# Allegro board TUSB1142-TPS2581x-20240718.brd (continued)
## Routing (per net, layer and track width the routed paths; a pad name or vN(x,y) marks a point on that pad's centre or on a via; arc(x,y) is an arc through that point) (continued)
A_UDN_SW: length 33.1
  TOP w0.127: v1(31.88,2.04) 32.13,2.3 32.13,3 32.04,3.09 F_TYPEC2.B7 ; v1(32.41,7.51) 33.24,7.51 33.66,7.09 33.66,6.43 32.79,5.55 F_TYPEC2.A7
  BOTTOM w0.127: v1(31.88,2.04) 32.13,2.29 32.13,2.91 30.45,4.59 30.45,6.7 31.27,7.51 v1(32.41,7.51) 32.82,7.1 33.14,7.1 33.62,7.58 33.62,8.94 33.44,9.12 33.44,9.5 33.62,9.68 33.62,10.06 33.44,10.24 33.44,10.62 33.62,10.8 33.62,11.18 33.44,11.36 33.44,11.74 33.62,11.91 33.62,13.76 34.6,14.73 34.6,14.98 34.87,15.25 35.12,15.25 35.39,15.52 35.39,15.77 35.66,16.04 35.91,16.04 36.19,16.32 36.84,16.32 37.01,16.5 37.4,16.5 37.57,16.32 38.6,16.32 40,14.93 U0905.1 41.37,14.93 42.16,14.14 42.41,14.14 L0901.4 42.76,14.48 R0905.2
A_UDP_SW: length 33.1
  TOP w0.127: F_TYPEC2.A6 32.29,5.66 32.6,5.97 32.77,5.97 33.36,6.56 33.36,6.96 33.11,7.21 32.74,7.21 32.41,6.88 v1(32.41,6.7) ; F_TYPEC2.B6 32.54,3.09 32.44,2.99 32.44,2.3 v1(32.69,2.04)
  BOTTOM w0.127: v1(32.69,2.04) 32.43,2.3 32.43,3.04 32.09,3.38 32.09,3.63 31.82,3.9 31.57,3.9 30.75,4.72 30.75,5.07 30.93,5.25 30.93,5.63 30.75,5.8 30.75,6.57 31.39,7.21 31.9,7.21 v1(32.41,6.7) 32.51,6.8 33.27,6.8 33.93,7.46 33.93,13.63 36.32,16.02 38.48,16.02 39.92,14.57 39.92,13.94 U0905.3 41.37,13.05 42.16,13.83 42.41,13.83 L0901.3 42.76,13.49 R0906.2
A_URXN_SW1_R: length 12.7
  TOP w0.127: F_TYPEC2.B10 30.54,3.09 30.45,3.01 30.45,2.29 v1(30.7,2.04) ; C0904.2 29.5,11.69 29.5,11.41 R0901.1 29.5,10.98 29.5,10.24 29.59,10.14 U0902.9 U0902.2 29.59,8.66 29.51,8.57 29.51,7.87 v1(29.75,7.63)
  BOTTOM w0.127: v1(30.7,2.04) 30.45,2.29 30.45,3.67 29.46,4.67 29.46,7.34 v1(29.75,7.63)
A_URXN_SW2_R: length 10.3
  TOP w0.127: F_TYPEC2.A10 34.29,5.52 34.38,5.62 34.38,7.07 35.41,8.1 35.41,8.54 35.32,8.64 U0901.1 U0901.10 35.32,10.14 35.41,10.24 35.41,13.52 R0903.1 35.41,13.95 35.41,14.36 C0911.2
A_URXP_SW1_R: length 12.8
  TOP w0.127: F_TYPEC2.B11 30.04,3.09 30.14,2.98 30.14,2.3 v1(29.88,2.04) ; C0912.2 29.19,11.69 29.19,11.41 R0902.1 29.19,10.98 29.19,10.24 29.09,10.14 U0902.10 U0902.1 29.09,8.69 29.2,8.58 29.2,7.89 v1(28.94,7.63)
  BOTTOM w0.127: v1(29.88,2.04) 30.14,2.3 30.14,3.55 29.15,4.54 29.15,7.41 v1(28.94,7.63)
A_URXP_SW2_R: length 10.3
  TOP w0.127: F_TYPEC2.A11 34.79,5.52 34.69,5.62 34.69,6.95 35.72,7.98 35.72,8.56 35.82,8.66 U0901.2 U0901.9 35.82,10.09 35.72,10.19 35.72,13.52 R0904.1 35.72,13.95 35.72,14.36 C0919.2
A_UTXN_SW1_R: length 8.9
  TOP w0.127: C0914.2 33.36,11.31 33.36,10.94 33.03,10.61 31.15,10.61 31,10.46 31,10.24 31.09,10.14 U0902.6 U0902.5 31.09,8.69 31.01,8.61 31.01,6.42 30.69,6.1 30.69,5.64 30.79,5.55 F_TYPEC2.A3
A_UTXN_SW2_R: length 12.4
  TOP w0.127: v1(33.88,2.04) 34.13,2.29 34.13,3 34.04,3.09 F_TYPEC2.B3 ; C0910.2 36.91,10.8 36.91,10.27 36.82,10.17 U0901.7 U0901.4 36.82,8.66 36.93,8.55 36.93,7.87 v1(36.66,7.6)
  BOTTOM w0.127: v1(33.88,2.04) 34.13,2.29 34.13,3.95 35.86,5.68 35.86,6.04 36.9,7.08 36.9,7.36 v1(36.66,7.6)
A_UTXP_SW1_R: length 8.9
  TOP w0.127: C0907.2 33.05,11.31 33.05,11.07 32.9,10.91 31.02,10.91 30.69,10.58 30.69,10.24 30.59,10.14 U0902.7 U0902.4 30.59,8.69 30.71,8.57 30.71,6.55 30.38,6.23 30.38,5.64 30.29,5.54 F_TYPEC2.A2
A_UTXP_SW2_R: length 12.4
  TOP w0.127: v1(37.47,7.6) 37.23,7.85 37.23,8.58 37.32,8.66 U0901.5 U0901.6 37.32,10.14 37.22,10.24 37.22,10.8 C0918.2 ; v1(34.7,2.04) 34.44,2.3 34.44,2.99 34.54,3.09 F_TYPEC2.B2
  BOTTOM w0.127: v1(37.47,7.6) 37.21,7.34 37.21,6.95 36.16,5.91 36.16,5.55 34.44,3.83 34.44,2.3 v1(34.7,2.04)
AMBER_PWR_LED#: length 70.8
  TOP w0.127: CN1.B36 21.09,38.03 22.98,39.92 v1(22.98,40.91)
  L3_IN1 w0.127: 59.58,54.93 44.93,54.93 38.25,61.61 24.15,61.61 20.52,57.98 18.46,57.98 18,57.52 18,43.94 20.21,41.73 22.16,41.73 v1(22.98,40.91)
AN_USB2_PB_EQ: length 1.5
  TOP w0.127: R0909.1 24.12,57.85 v1(24.2,57.78) 24.54,57.44 U0903.6
AN_USB2_PB_VREG: length 1.8
  TOP w0.127: U0903.11 v1(25.34,54.75) 25.14,54.55 C0905.1
AR_B_DFP_CC1: length 33.2
  TOP w0.178: 46.35,17.23 46.1,17.49 U0801.24
  TOP w0.254: F_TYPEC2.A5 31.79,5.85 v1(31.91,5.98) ; 46.35,17.23 47.47,17.23 47.72,16.98 C0811.1 v1(47.72,15.03)
  BOTTOM w0.254: v1(31.91,5.98) 32.3,5.98 33.24,5.04 33.66,5.04 34.37,5.75 34.37,6.49 35.25,7.37 35.25,13.43 36.05,14.23 36.4,14.23 C3411.1 37.1,14.65 37.38,14.93 U0905.6 38.55,14.93 39.21,14.27 39.21,12.97 39.97,12.21 46.32,12.21 47.97,13.86 47.97,14.77 v1(47.72,15.03)
AR_B_DFP_CC2: length 32.7
  TOP w0.203: 47,17.65 46.62,18.03 U0801.25
  TOP w0.254: F_TYPEC2.B5 33.04,2.83 v1(32.99,2.77) ; v1(48.53,15.08) C0810.1 48.53,16.71 47.59,17.65 47,17.65
  BOTTOM w0.254: v1(48.53,15.08) 48.36,14.9 48.36,13.7 46.48,11.83 39.64,11.83 U0905.4 37.89,13.05 37.61,13.33 C3410.1 36.81,13.84 36.2,13.84 35.64,13.28 35.64,7.21 34.75,6.33 34.75,5.59 v2(33.13,3.97) 33.13,2.92 v1(32.99,2.77)
AR_U2DM_A_ESD: length 40.5
  TOP w0.127: F_TYPEC1.A7 10.31,5.55 11.18,6.43 11.18,7.09 10.76,7.51 v1(9.93,7.51) ; F_TYPEC1.B7 9.56,3.21 9.64,3.12 9.64,2.29 v1(9.4,2.04)
  BOTTOM w0.127: v1(9.4,2.04) 9.65,2.29 9.65,2.91 7.97,4.59 7.97,6.7 8.79,7.51 v1(9.93,7.51) 10.34,7.1 10.89,7.1 11.37,7.59 11.37,9.58 12.24,10.46 12.24,10.71 12.51,10.98 12.76,10.98 13.03,11.25 13.03,11.5 13.3,11.77 13.55,11.77 14.3,12.51 16.92,12.51 17.1,12.69 17.48,12.69 17.65,12.51 18.04,12.51 18.21,12.69 18.59,12.69 18.77,12.51 20.31,12.51 21.27,13.47 21.27,13.72 21.54,13.99 21.79,13.99 22.8,15 22.8,15.25 23.07,15.52 23.32,15.52 23.74,15.94 26.66,15.94 27.68,14.93 U1203.1 29.05,14.93 29.84,14.14 30.1,14.14 L1201.4 30.44,14.48 R1206.2
AR_U2DP_A_ESD: length 40.5
  TOP w0.127: F_TYPEC1.B6 10.06,3.24 9.95,3.13 9.95,2.31 v1(10.21,2.04) ; v1(9.93,6.7) 9.93,6.88 10.26,7.21 10.63,7.21 10.88,6.96 10.88,6.56 10.29,5.97 10.12,5.97 9.81,5.66 F_TYPEC1.A6
  BOTTOM w0.127: R1205.2 30.44,13.49 L1201.3 30.1,13.83 29.84,13.83 29.05,13.05 U1203.3 27.68,13.86 27.68,14.5 26.54,15.64 23.87,15.64 20.44,12.21 14.43,12.21 11.68,9.46 11.68,7.46 11.02,6.8 10.03,6.8 v1(9.93,6.7) 9.42,7.21 8.91,7.21 8.27,6.57 8.27,5.8 8.45,5.63 8.45,5.25 8.27,5.07 8.27,4.72 9.09,3.9 9.34,3.9 9.61,3.63 9.61,3.38 9.95,3.04 9.95,2.3 v1(10.21,2.04)
AR_U3RXN_A_ESD_1: length 13.4
  TOP w0.102: C1203.2 8,11.65 8,11.45 R1204.1 7.99,10.94 7.99,10.25 8.13,10.12 U1202.9 U1202.2 8.13,8.7 7.99,8.55 7.99,8.26 7.75,8.03 7.48,8.03 7.34,7.89 7.34,7.56 v1(7.64,7.27) ; F_TYPEC1.B10 8.06,3.22 7.92,3.08 7.92,2.34 v1(8.22,2.04)
  BOTTOM w0.102: v1(7.64,7.27) 7.34,6.97 7.34,6.55 7.03,6.24 7.03,4.64 7.92,3.75 7.92,2.34 v1(8.22,2.04)
AR_U3RXN_A_ESD_2: length 10.7
  TOP w0.102: F_TYPEC1.A10 11.81,5.54 11.94,5.68 11.94,6.14 13.99,8.19 13.99,8.53 13.85,8.67 U1201.1 U1201.10 13.85,10.17 13.99,10.3 13.99,10.48 13.8,10.67 11.89,10.67 11.63,10.94 11.63,11.32 R1202.1 11.63,11.83 11.63,12.03 C1506.2
AR_U3RXP_A_ESD_1: length 13.4
  TOP w0.102: F_TYPEC1.B11 7.56,3.22 7.69,3.08 7.69,2.33 v1(7.4,2.04) ; C1202.2 7.77,11.65 7.77,11.45 R1203.1 7.77,10.94 7.77,10.3 7.63,10.17 U1202.10 U1202.1 7.63,8.68 7.76,8.55 7.76,8.36 7.66,8.26 7.39,8.26 7.12,7.98 7.12,7.56 v1(6.82,7.27)
  BOTTOM w0.102: v1(7.4,2.04) 7.69,2.33 7.69,3.66 6.8,4.55 6.8,6.33 7.12,6.65 7.12,6.97 v1(6.82,7.27)
AR_U3RXP_A_ESD_2: length 10.7
  TOP w0.102: F_TYPEC1.A11 12.31,5.54 12.17,5.67 12.17,6.05 14.22,8.09 14.22,8.53 14.35,8.66 U1201.2 U1201.9 14.35,10.17 14.22,10.3 14.22,10.58 13.89,10.9 11.98,10.9 11.86,11.03 11.86,11.32 R1201.1 11.86,11.83 11.86,12.03 C1505.2
AUD_AGND: length 12.9
  TOP w0.508: C0510.2 v1(37.69,49.27)
  L4_VCC w0.508: FP_AUDIO.11 32.8,48.01 ; FP_AUDIO.11 31.49,48.01 ; FP_AUDIO.11 31.49,49.32 ; FP_AUDIO.11 32.8,49.32 ; 31.49,52.01 FP_AUDIO.7 ; FP_AUDIO.7 31.49,53.32 ; FP_AUDIO.7 32.8,52.01 ; FP_AUDIO.7 32.8,53.32 ; 34.8,59.32 FP_AUDIO.2 33.49,59.32 ; 31.49,46.01 FP_AUDIO.13 ; FP_AUDIO.13 31.49,47.32 ; FP_AUDIO.13 32.8,47.32
  vias: v1(39.75,48.66) v1(40,53.61) v1(44.83,48.66) v1(46.1,52.09) v1(49.91,48.66) v1(51.18,52.09) v1(54.99,48.66) v1(56.26,52.09)
AUD_FP_LINE2_JD: length 26.5
  BOTTOM w0.305: FP_AUDIO.8 38.28,52.67 40.76,50.18 59.58,50.18
AUD_FP_MIC2_JD: length 27.1
  L3_IN1 w0.305: 59.58,50.56 39.87,50.56 35.77,54.67 FP_AUDIO.6
AUD_FP_MIC_P: length 22.9
  TOP w0.305: R0503.2 v1(39.26,53.12) 39.26,52.97 38.88,52.6 R0502.2
  L3_IN1 w0.305: v1(39.26,53.12) 41.05,51.33 59.58,51.33
AUD_FP_MICIN_IN_R_L: length 14.8
  TOP w0.305: FP_AUDIO.1 30.52,57.05 30.52,52.67 31.57,51.63 36.84,51.63 R0502.1
AUD_FP_MICIN_IN_R_R: length 9.9
  TOP w0.305: R0503.1 37.15,53.74 37.05,53.64 31.59,53.64 31.13,54.09 31.13,55.66 FP_AUDIO.3
AUD_FP_SLEEVE_GND: length 26.5
  BOTTOM w0.305: 59.58,49.42 39.87,49.42 38.96,50.33 35.81,50.33 FP_AUDIO.12
AUD_LINE2_OUT_L_R: length 29.3
  TOP w0.305: FP_AUDIO.9 38.2,50.67 v1(40.63,53.1)
  BOTTOM w0.305: 59.58,50.94 42.79,50.94 v2(41.69,52.04) v1(40.63,53.1)
AUD_LINE2_OUT_R_R: length 29.5
  L3_IN1 w0.305: 59.58,49.8 38.86,49.8 34.97,53.69 33.13,53.69 FP_AUDIO.5
BREATH_LED#: length 70.3
  TOP w0.127: v1(22.35,40.91) 22.35,39.64 21.34,38.63 CN1.B35
  L3_IN1 w0.127: 59.58,55.22 45.04,55.22 38.37,61.89 22.98,61.89 19.38,58.28 18.36,58.28 17.67,57.6 17.67,43.82 20.01,41.48 21.78,41.48 v1(22.35,40.91)
CRITI_PCH_RSMRST#: length 67.4
  TOP w0.127: CN1.A30 14.13,41.63 v1(13.58,42.18)
  L3_IN1 w0.127: 59.58,55.49 45.16,55.49 38.47,62.17 22.9,62.17 19.27,58.54 18.21,58.54 17.39,57.73 17.39,44.85 16.63,44.09 13.96,44.09 13.58,43.71 v1(13.58,42.18)
DG_USB2_PB_DC_BST: length 5.2
  TOP w0.127: R0907.2 24.63,51.87 24.63,53.27 R0908.1 23.85,54.05 v1(23.85,55.16) 24.18,55.49 U0903.9
DG_USB2_PB_RST#: length 3.7
  TOP w0.127: U0903.5 24.94,58.33 C0902.1 R0910.2 27.29,58.53 v1(27.36,58.45)
ECALIVE_LED_GATE: length 70.6
  TOP w0.127: v1(12.82,41.04) 14.03,39.83 CN1.A33
  L3_IN1 w0.127: v1(12.82,41.04) 12.82,42.31 13.2,42.69 13.2,43.83 13.71,44.34 13.71,44.72 14.47,45.48 16.37,45.48 17.14,46.25 17.14,58.06 18.68,59.59 18.68,60.78 20.32,62.42 38.62,62.42 45.3,55.74 59.58,55.74
FRONT_TYPEC_CC_RDY: length 13
  TOP w0.127: v1(20.57,33.93) 21.71,35.07 21.71,37.71 23.49,39.49 23.49,41.19 23.26,41.42 22.07,41.42 21.67,41.02 21.67,40.72 20.78,39.83 CN1.B33
GPI_FRONT_CABLE1_N: length 31.8
  TOP w0.127: J1.18 4.45,41.67 3.42,42.69 2.53,42.69 2.03,43.2 2.03,60.48 3.04,61.49 4.44,61.49 7.66,58.27 R0613.1
GPI_FRONT_CABLE2_N: length 3.5
  TOP w0.127: v1(12.57,43.83) 12.57,44.24 R7422.2 13.5,44.64 14.09,45.23 CN1.A24
GPO_CHAR_CB: length 31.6
  TOP w0.127: CN1.B28 21.93,42.83 v1(22.56,42.2) ; v1(42.03,39.9) R0812.2 R74425.1
  L3_IN1 w0.127: v1(42.03,39.9) 41.57,39.44 26.38,39.44 23.61,42.2 v1(22.56,42.2)
GPO_CHAR_SMART_CDP: length 45.8
  TOP w0.127: R74426.1 v1(50.29,40.4) ; CN1.B30 21.34,41.63 v1(21.9,42.19)
  L3_IN1 w0.127: v1(21.9,42.19) 22.4,42.69 23.49,42.69 26.49,39.69 40.56,39.69 41.27,40.4 v1(50.29,40.4)
I2C_FIO_RETIMER_SCL: length 66.8
  TOP w0.127: CN1.A36 14.46,38.03 14.29,38.2 13.98,38.2 v1(13.69,37.92) 13.41,38.2 11.08,38.2 8.5,35.63 8.5,26.47 R1007.1
  BOTTOM w0.127: v1(13.69,37.92) 13.98,38.2 21.14,38.2 23.08,36.26 26.89,36.26 28.59,34.56 34.99,34.56 36.44,33.11 53.53,33.11 55.51,31.13 59.58,31.13
I2C_FIO_RETIMER_SDA: length 67.2
  TOP w0.127: CN1.A35 14.73,38.63 14.56,38.46 13.96,38.46 v1(13.69,38.73) 13.42,38.46 10.97,38.46 8.25,35.73 8.25,26.47 R1009.1
  BOTTOM w0.127: 59.58,31.39 55.62,31.39 53.64,33.37 36.54,33.37 35.1,34.81 28.7,34.81 26.99,36.52 23.18,36.52 21.24,38.46 13.96,38.46 v1(13.69,38.73)
LD_DET#: length 2.1
  TOP w0.127: U1101.20 28.3,23.18 v1(29.03,23.18) 29.37,23.18 R1106.1
MUX_SLP_S0_N: length 4.8
  TOP w0.127: U1001.4 13.85,20.61 14.73,21.48 v1(14.73,21.86) R1040.2
POWER_SW_IN#: length 64.8
  TOP w0.127: CN1.A23 13.8,45.83 v1(13.71,45.74)
  L3_IN1 w0.127: v1(13.71,45.74) 16.2,45.74 16.89,46.42 16.89,58.16 18.42,59.7 18.42,60.89 20.21,62.68 38.73,62.68 45.41,56 59.58,56
POWERSHARE_EN_N: length 53.7
  TOP w0.127: U0801.5 44.5,21.81 44.06,22.25 44.06,24.66 45.46,26.05 v1(45.46,39.9) ; v1(14.22,42.23) CN1.A29
  L3_IN1 w0.127: v1(45.46,39.9) 44.49,38.93 24.45,38.93 23.61,39.77 20.95,39.77 17.9,42.82 14.8,42.82 v1(14.22,42.23)
Q3400_6: length 1.7
  TOP w0.127: Q1001.6 4.45,23.61 4.8,23.26 v1(4.9,23.26) R1018.2
REAR_TYPEC1_CC_RDY: length 3.3
  TOP w0.127: R1016.2 R1101.2 4.12,22.44 4.12,22.57 v1(3.42,23.28) 3.42,23.36 3.8,23.75 Q1001.5
SATA_LED_OUT: length 60.4
  TOP w0.127: CN1.B29 v1(20.89,42.23)
  L3_IN1 w0.127: 59.58,54.6 44.75,54.6 38.07,61.28 24.25,61.28 22.68,59.71 22.68,54.8 23.46,54.02 23.46,44.51 21.19,42.23 v1(20.89,42.23)
SLP_S3_N: length 26.5
  TOP w0.127: v1(23.62,32.4) 23.62,37.61 24.63,38.63 24.63,42.28 22.88,44.03 CN1.B26 ; R1102.1 v1(17.9,24.78)
  BOTTOM w0.127: v1(17.9,24.78) 18.41,25.29 18.41,25.95 v2(23.29,30.83) 23.62,31.16 v1(23.62,32.4)
SLP_S4_N: length 66.8
  TOP w0.127: v1(53.46,38.63) 53.46,36.66 59.58,30.54 ; CN1.B27 22.98,43.43 24.25,42.16 24.25,39.13 v1(23.62,38.5) 22.55,37.43 22.55,29.47 R1105.1
  L3_IN1 w0.127: v1(23.62,38.5) 23.74,38.63 v1(53.46,38.63) 53.84,38.24 59.58,38.24
TC_RX1N_TYPEC_1: length 7
  TOP w0.102: U1001.31 8.86,18.66 8.78,18.58 8.78,16.93 8,16.15 8,12.77 C1203.1
TC_RX1P_TYPEC_1: length 7
  TOP w0.102: U1001.30 8.46,18.68 8.55,18.59 8.55,17.02 7.77,16.24 7.77,12.77 C1202.1
TC_RX2N_TYPEC_1: length 6.5
  TOP w0.102: C1506.1 11.63,13.15 11.63,17.3 10.95,17.98 10.95,18.58 10.86,18.66 U1001.36
TC_RX2P_TYPEC_1: length 6.5
  TOP w0.102: U1001.37 11.26,18.65 11.18,18.57 11.18,18.07 11.86,17.39 11.86,13.15 C1505.1
TC_TX1N_TYPEC_1: length 11.1
  TOP w0.102: C3408.2 9.57,15.08 9.57,14.11 9.49,14.04 9.49,10.28 9.63,10.15 U1202.6 U1202.5 9.63,8.74 9.49,8.6 9.49,8.14 8.45,7.1 8.45,6.73 8.17,6.45 8.17,5.67 8.31,5.54 F_TYPEC1.A3
TC_TX1P_TYPEC_1: length 11.1
  TOP w0.102: C3409.2 9.34,15.08 9.34,14.21 9.27,14.13 9.27,10.3 9.13,10.16 U1202.7 U1202.4 9.13,8.74 9.27,8.6 9.27,8.23 8.22,7.19 8.22,6.83 7.94,6.54 7.94,5.67 7.81,5.54 F_TYPEC1.A2
TC_TX2N_TYPEC_1: length 13.7
  TOP w0.102: v1(11.4,2.04) 11.7,2.34 11.7,3.07 11.56,3.21 F_TYPEC1.B3 ; v1(15.2,7.68) 15.49,7.97 15.49,8.55 15.35,8.69 U1201.4 U1201.7 15.35,10.14 15.49,10.28 15.49,10.76 C3407.2
  BOTTOM w0.102: v1(11.4,2.04) 11.7,2.34 11.7,3.93 13.42,5.65 13.42,6.26 13.99,6.82 15.19,6.82 15.49,7.12 15.49,7.39 v1(15.2,7.68)
TC_TX2P_TYPEC_1: length 13.7
  TOP w0.102: v1(16.01,7.68) 15.72,7.97 15.72,8.55 15.85,8.69 U1201.5 U1201.6 15.85,10.14 15.72,10.28 15.72,10.76 C3406.2 ; v1(12.22,2.04) 11.93,2.33 11.93,3.09 12.06,3.21 F_TYPEC1.B2
  BOTTOM w0.102: v1(16.01,7.68) 15.72,7.39 15.72,7.03 15.28,6.6 14.08,6.6 13.65,6.16 13.65,5.55 11.93,3.84 11.93,2.33 v1(12.22,2.04)
TH_DIODE_FRONT_AN: length 9
  TOP w0.127: Q0608.E 10.42,49.77 10.42,47.41 10.69,47.13 11.29,47.13 C0611.2 12.37,47.13 v1(12.57,47.13) 13.21,47.13 C0610.2 13.75,47.18 14.61,47.18 14.75,47.03 CN1.A21
TH_DIODE_FRONT_CA: length 12.1
  TOP w0.127: CN1.A20 14.77,47.63 14.56,47.43 13.75,47.43 C0610.1 12.04,47.72 C0611.1 11.29,47.39 10.8,47.39 10.67,47.52 10.67,49.33 v1(11.91,50.56) Q0608.C 10.96,52.32 Q0608.B
TPS25810_AUDIO: length 2.2
  TOP w0.127: R1110.2 29.59,20.59 v1(29.2,20.97) 28.68,21.49 U1101.17
TPS25810_DEBUG: length 3.2
  TOP w0.127: R1109.2 29.2,19.58 v1(29.13,19.5) 28.44,19.5 27.41,20.53 U1101.16
TPS25814_POL: length 49
  TOP w0.127: U0801.13 41.29,19.38 R7431.2 40.63,18.72 v1(40.63,17.16) ; CN1.B32 21.02,40.43 21.42,40.82 21.42,41.13 21.97,41.67 23.36,41.67 23.74,41.29 23.74,39.39 21.97,37.61 v1(21.97,33.93)
  BOTTOM w0.127: v1(40.63,17.16) 40.63,22.62 39.87,23.38 39.87,28.41 38.09,30.2 32.47,30.2 31.02,31.64 v2(30.34,31.64) 27.55,34.43 22.47,34.43 v1(21.97,33.93)
U1_A0: length 11
  TOP w0.127: R1002.2 5.58,11.74 5.58,13.01 R1026.2 6.01,13.59 6.01,14.06 v1(6.29,14.34) 6.34,14.39 R1025.1 ; U1001.35 10.46,18.16 v1(10.47,18.15)
  L3_IN1 w0.127: v1(10.47,18.15) 10.1,18.15 v1(6.29,14.34)
U1_A1: length 12.1
  TOP w0.127: U1001.2 14.3,19.81 16.76,22.27 v1(16.76,22.75) R1020.2 17.27,24.87 17.27,26.01 R1038.2 17.39,27.16 17.39,28.17 R1036.1
U1_AEQCFG: length 15.3
  TOP w0.127: v1(2.92,14.24) 2.92,13.64 R1022.2 2.53,13.01 2.53,11.74 R1039.2 2.53,10.72 2.53,9.45 R1021.1 ; v1(6.67,20.51) 6.67,20.97 7.11,21.41 U1001.23
  L3_IN1 w0.127: v1(2.92,14.24) 4.82,16.15 4.82,17.16 5.84,18.18 5.84,18.94 6.67,19.78 v1(6.67,20.51)
U1_AR_A_DFP_CC1: length 31.7
  TOP w0.254: v1(26.79,14.45) 26.04,14.45 24.76,15.73 24.76,17.9 24.48,18.18 C1115.1 24.48,19.91 24.91,20.34 U1101.11 ; v1(9.43,5.98) 9.31,5.85 F_TYPEC1.A5
  BOTTOM w0.254: v1(26.79,14.45) 26.73,14.45 26.26,14.93 U1203.6 24.64,14.93 C1207.1 19.26,9.54 13.96,9.54 v2(13.71,9.29) 13.46,9.03 13.46,7.95 11.91,6.4 11.91,5.72 11.37,5.18 10.23,5.18 v1(9.43,5.98)
U1_AR_A_DFP_CC2: length 32.3
  TOP w0.254: v1(26.82,13.53) 27.43,14.14 27.43,14.77 27.07,15.13 25.9,15.13 25.14,15.89 25.14,17.92 25.62,18.41 C1114.1 25.62,19.29 25.91,19.58 U1101.13 ; F_TYPEC1.B5 10.56,2.83 v1(10.51,2.77)
  BOTTOM w0.254: v1(26.82,13.53) 26.33,13.05 U1203.4 24.67,13.05 C1208.1 23.23,12.88 19.51,9.16 14.73,9.16 13.84,8.27 13.84,7.79 12.29,6.24 12.29,5.56 v2(10.68,3.95) 10.68,2.95 v1(10.51,2.77)
U1_CEQ0: length 15.9
  TOP w0.127: v1(5.35,14.39) 5.07,14.11 R1033.2 4.57,13.01 4.57,11.74 R1029.2 4.57,10.72 4.57,9.45 R1034.1 ; U1001.38 11.66,18.22 v1(11.73,18.15)
  L3_IN1 w0.127: v1(5.35,14.39) 5.94,13.81 6.6,13.81 7.11,14.32 7.11,14.8 9.56,17.25 10.83,17.25 v1(11.73,18.15)
U1_CEQ1: length 13.5
  TOP w0.127: v1(3.68,14.24) 4.06,13.86 R1001.2 3.55,13.01 3.55,11.74 R1024.2 3.55,10.72 3.55,9.45 R1023.1 ; v1(7.87,17.29) 7.87,17.92 8.06,18.12 U1001.29
  L3_IN1 w0.127: v1(7.87,17.29) 5.89,15.31 4.74,15.31 v1(3.68,14.24)
U1_EQCFG: length 11.2
  TOP w0.127: R1005.1 16.25,28.3 16.25,27.03 R1030.2 16.25,26.01 16.25,24.87 R1037.2 15.41,24.03 v1(15.41,23.69) 15.41,21.33 14.29,20.21 U1001.3
U1_MODE: length 9.5
  TOP w0.127: R1035.1 12.82,28.3 12.82,27.03 R1031.2 12.82,26.01 12.82,24.87 R1032.2 11.72,23.77 v1(11.68,23.77) ; U1001.17 v1(9.26,23.51)
  L3_IN1 w0.127: v1(9.26,23.51) 11.42,23.51 v1(11.68,23.77)
U1_MUX_I2C_EN: length 6.7
  TOP w0.127: U1001.26 7.02,20.21 6.22,19.41 6.22,18.56 v1(6.34,18.43) 6.34,18.39 R1004.1 5.84,16.87 5.84,15.6 C1009.2
U1_PCH_EC_I2C_SCL_CYPD: length 16.7
  TOP w0.127: U1001.21 7.19,22.21 7.06,22.34 7.06,22.56 v1(7.31,22.8) 7.11,23 7.11,23.47 R1007.2 ; R1013.2 3.78,19.11 3.78,17.84 R1011.2 4.15,17.19 v1(4.15,16.64) 4.15,16.46 4.29,16.32 R1006.1
  L3_IN1 w0.127: v1(7.31,22.8) 7.31,22.57 6.67,21.94 5.89,21.94 3.78,19.83 3.78,17 v1(4.15,16.64)
U1_PCH_EC_I2C_SDA_CYPD: length 17
  TOP w0.127: R1008.1 3.27,16.03 v1(2.69,16.62) 2.69,16.75 R1010.2 2.76,17.84 2.76,19.11 R1012.2 ; U1001.22 7.11,21.81 6.6,22.32 v1(6.6,22.55) 6.85,22.8 6.85,23.62 7.87,24.63 R1009.2
  L3_IN1 w0.127: v1(6.6,22.55) 6.27,22.22 5.71,22.22 2.69,19.2 v1(2.69,16.62)
U1_TPS25810_POL: length 37.7
  TOP w0.127: v1(29.08,21.73) 28.82,21.99 U1101.18 ; v1(3.17,24.93) 3.8,25.57 Q1001.2 3.8,26.31 4.31,26.81 5.33,26.81 5.54,26.6 R1103.1 R1017.2 6.38,24.45 R1019.2
  L3_IN1 w0.127: v1(29.08,21.73) 27.49,23.32 23.93,23.32 23.52,22.9 17.54,22.9 15.26,25.18 15.26,26.43 14.37,27.32 5.56,27.32 v1(3.17,24.93)
U1_TPS25810_POL_R: length 6.2
  TOP w0.127: R1013.1 R1014.1 5.7,20.45 v1(6,20.76) 6.55,21.3 6.55,21.86 6.09,22.32 6.09,22.78 6.38,23.07 R1018.1 6.38,23.44 R1019.1
U1_TPS25810_UFP_R: length 7.7
  TOP w0.127: 3.27,21.42 3.19,21.5 1.88,21.5 v1(1.83,21.55) 1.52,21.86 1.52,24.02 3.15,25.66 Q1001.3 ; 3.27,21.42 R1015.1 ; 3.27,21.42 R1012.1
U1_TX1N: length 3.4
  TOP w0.102: U1001.34 10.06,18.65 9.98,18.56 9.98,16.86 9.57,16.45 9.57,16.2 C3408.1
U1_TX1P: length 3.4
  TOP w0.102: C3409.1 9.34,16.2 9.34,16.55 9.75,16.95 9.75,18.58 9.66,18.67 U1001.33
U1_TX2N: length 8.9
  TOP w0.102: C3407.1 15.49,11.88 15.49,14.04 14.12,15.42 14.12,16.31 12.16,18.26 12.16,18.53 12.06,18.63 U1001.39
U1_TX2P: length 8.9
  TOP w0.102: C3406.1 15.72,11.88 15.72,14.14 14.35,15.51 14.35,16.4 12.39,18.36 12.39,18.58 12.46,18.66 U1001.40
U1_VIO_SEL: length 9.7
  TOP w0.127: R1027.1 14.09,28.3 14.09,27.03 R1028.2 14.09,26.01 14.09,24.87 R1003.2 v1(13.58,23.64) 13.18,23.23 10.74,23.23 10.46,22.96 U1001.14
U3500_UFP_N: length 39.8
  TOP w0.127: v1(1.97,23.12) 2.37,22.73 3.5,22.73 3.75,22.47 3.75,21.96 4.27,21.44 R1101.1 ; U1101.19 29.04,22.49 v1(29.07,22.46) R1104.1
  L3_IN1 w0.127: v1(1.97,23.12) 1.97,24.73 5.84,28.59 14.22,28.59 16.25,26.56 16.25,24.55 17.63,23.18 23.41,23.18 23.8,23.57 27.6,23.57 28.71,22.46 v1(29.07,22.46)
U7401_CAP_EXT: length 3.8
  TOP w0.127: C0714.1 31.15,23.26 31.49,23.26 31.97,22.78 31.97,22.12 v1(32.18,21.91) 32.81,21.91 33.04,22.15 U0701.16
U7401_EN: length 2.5
  TOP w0.127: U0701.33 v1(38.5,22.85) 38.66,22.85 39.07,23.26 R0701.2
U7401_EQA: length 6.5
  TOP w0.127: v1(39.64,17.14) 39.64,18.69 39.11,19.22 R0710.2 39.62,19.74 39.62,20.88 R0702.1 38.84,21.66 38.63,21.66 38.14,22.15 U0701.31
U7401_EQB: length 9.8
  TOP w0.127: U0701.24 35.75,21.25 35.75,18.88 v1(35.55,18.69) ; R0704.1 v1(30.6,17.62) 29.97,16.98 R0712.2
  L3_IN1 w0.127: v1(30.6,17.62) 31.36,18.38 35.25,18.38 v1(35.55,18.69)
U7401_EQC: length 9.9
  TOP w0.127: v1(35.45,25.57) 35.38,25.5 U0701.7 ; R0706.1 40.72,25.93 39.58,25.93 R0714.2 v1(39.07,27.2)
  BOTTOM w0.127: v1(39.07,27.2) 38.69,26.81 v2(36.06,26.81) 35.45,26.2 v1(35.45,25.57)
U7401_EQD: length 7.8
  TOP w0.127: R0708.1 31.36,27.46 31.25,27.58 ; 31.25,27.58 31.24,27.59 31.24,27.8 31.36,27.93 R0716.2 ; 31.25,27.58 v1(31.24,27.58) ; v1(31.38,23.73) 31.91,23.73 32.58,23.05 32.81,23.05 33.02,22.85 U0701.14
  BOTTOM w0.127: v1(31.38,23.73) 31.26,23.84 v2(31.26,26.43) 31.26,27.54 31.24,27.56 v1(31.24,27.58)
U7401_FGA: length 5.6
  TOP w0.127: R0711.2 40.63,19.74 40.63,20.88 R0703.1 40.13,21.78 v1(39.77,22.14) 38.53,22.14 38.17,22.5 U0701.32
U7401_FGB: length 8.2
  TOP w0.127: U0701.23 35.4,21.25 35.4,19.51 v1(35.28,19.4) ; R0705.1 v1(30.6,18.64) 30.56,18.6 R0713.2
  L3_IN1 w0.127: v1(30.6,18.64) 34.52,18.64 v1(35.28,19.4)
U7401_FGC: length 8
  TOP w0.127: v1(38.6,25.93) 38.6,25.76 R0715.2 39.58,24.78 40.72,24.78 R0707.1 ; U0701.6 35.73,24.93 v1(36.09,25.29)
  BOTTOM w0.127: v1(36.09,25.29) 37.21,25.29 v2(37.33,25.16) 38.09,25.93 v1(38.6,25.93)
U7401_FGD: length 8.9
  TOP w0.127: R0717.2 30.58,28.07 v1(30.58,27.6) 30.35,27.37 R0709.1 ; U0701.15 33.32,22.49 32.57,22.48 v1(32.43,22.62)
  BOTTOM w0.127: v1(30.58,27.6) 30.58,27.54 30.62,27.5 30.62,24.61 v2(30.65,24.58) 30.65,23.46 30.91,23.21 31.85,23.21 v1(32.43,22.62)
USB1_USB32_RX_C_RE_N: length 10.2
  TOP w0.127: U1001.18 8.86,22.9 8.82,22.95 8.82,23.7 9.99,24.87 9.99,32.01 C1002.1
USB1_USB32_RX_C_RE_P: length 10.2
  TOP w0.127: U1001.19 8.46,22.96 8.51,23.01 8.51,23.82 9.68,25 9.68,32.01 C1001.1
USB1_USB32_TX_C_RE_N: length 13.8
  TOP w0.127: U1001.15 10.06,22.97 10.02,23.02 10.02,23.25 11.03,24.26 11.03,30.74 12.28,31.98 12.28,35.18 C1004.1
USB1_USB32_TX_C_RE_P: length 13.8
  TOP w0.127: C1003.1 11.97,35.18 11.97,32.11 10.73,30.87 10.73,24.39 9.71,23.37 9.71,22.94 9.66,22.89 U1001.16
USB2_P01_ESD_DN: length 6.9
  BOTTOM w0.102: USB3_F1.2 55.55,11.63 56.45,12.53 56.45,13.06 56.81,13.43 59.58,13.43
USB2_P01_ESD_DP: length 6.5
  BOTTOM w0.102: 59.58,13.2 56.91,13.2 56.68,12.97 56.68,12.55 57.55,11.68 USB3_F1.3
USB3_RX1_ESD_DP: length 1.6
  TOP w0.102: USB3_F1.6 59.27,11.36 59.43,11.52 59.43,11.98 59.58,12.14
USB3_TX1_ESD_DN: length 8.3
  TOP w0.102: USB3_F1.8 53.77,11.36 53.66,11.46 53.66,12.4 54.8,13.53 59.58,13.53
USB3_TX1_ESD_DP: length 8.6
  TOP w0.102: 59.58,13.76 54.7,13.76 53.44,12.49 53.44,11.46 53.33,11.36 USB3_F1.9
USB3_USB32_RX_RE_N: length 10.8
  TOP w0.127: C0904.1 29.51,12.72 29.51,12.98 33.57,17.05 33.57,20.57 33.93,20.93 33.93,21.05 33.98,21.1 U0701.19
USB3_USB32_RX_RE_P: length 10.8
  TOP w0.127: U0701.18 33.63,21.05 33.27,20.69 33.27,17.17 29.2,13.11 29.2,12.74 C0912.1
USB3_USB32_TX_RE_N: length 10
  TOP w0.127: U0701.22 35.03,20.24 34.54,19.75 34.54,16.15 33.33,14.94 33.33,12.37 C0914.1
USB3_USB32_TX_RE_P: length 10
  TOP w0.127: C0907.1 33.03,12.32 33.03,15.07 34.23,16.27 34.23,19.88 34.72,20.37 34.72,21.07 34.68,21.11 U0701.21
USB4_USB32_RX_RE_N: length 7
  TOP w0.127: C0911.1 35.41,15.4 35.41,16.31 36.56,17.46 36.56,19.78 36.09,20.26 36.09,21.13 36.08,21.14 U0701.25
USB4_USB32_RX_RE_P: length 7
  TOP w0.127: U0701.26 36.43,21.09 36.39,21.05 36.39,20.39 36.87,19.91 36.87,17.33 35.72,16.18 35.72,15.4 C0919.1
USB4_USB32_TX_RE_N: length 10.6
  TOP w0.127: U0701.28 37.13,21.1 37.17,21.05 37.17,20.95 37.97,20.16 37.97,13.66 36.91,12.6 36.91,11.84 C0910.1
USB4_USB32_TX_RE_P: length 10.6
  TOP w0.127: U0701.29 37.48,21.08 38.27,20.29 38.27,13.53 37.22,12.48 37.22,11.84 C0918.1
USB7_USB20_N: length 49.5
  TOP w0.127: v1(26.49,33.45) 26.82,33.77 26.82,34.6 26.64,34.78 26.64,35.16 26.82,35.34 26.82,35.87 26.64,36.05 26.64,36.43 26.82,36.61 26.82,37.14 26.64,37.32 26.64,37.7 26.82,37.88 26.82,47.06 22.96,50.92 22.96,53.26 21.83,54.38 20.5,54.38 20.35,54.23 CN1.B9
  BOTTOM w0.127: v1(26.49,33.45) 26.82,33.12 26.82,31.94 27.88,30.88 27.88,23.94 28.16,23.66 28.16,22.34 27.99,22.16 27.99,21.78 28.16,21.61 28.16,21.23 27.99,21.05 27.99,20.67 28.16,20.49 28.16,20.11 27.99,19.93 27.99,19.55 28.16,19.37 28.16,17.9 29.55,16.51 30.94,16.51 32.2,15.26 32.2,14.34 32,14.14 31.61,14.14 L1201.1 31.27,14.48 R1206.1
USB7_USB20_P: length 49.5
  TOP w0.127: v1(27.3,33.45) 27.12,33.63 27.12,47.18 23.26,51.05 23.26,53.38 21.96,54.68 20.49,54.68 20.34,54.83 CN1.B8
  BOTTOM w0.127: R1205.1 31.27,13.49 L1201.2 31.62,13.83 32.13,13.83 32.51,14.22 32.51,15.38 31.07,16.82 29.67,16.82 28.47,18.03 28.47,23.79 28.19,24.07 28.19,31 27.12,32.07 27.12,33.27 v1(27.3,33.45)
USB7_USB31_RX_N: length 40.8
  TOP w0.127: v1(21.54,52.37) 21.31,52.6 20.53,52.6 20.35,52.43 CN1.B12 ; C1002.2 9.99,33.05 9.99,33.4 v1(10.24,33.65)
  BOTTOM w0.127: v1(10.24,33.65) 9.96,33.93 9.96,37.22 9.57,37.61 9.57,54.35 9.84,54.62 10.09,54.62 10.36,54.89 10.36,55.14 10.63,55.41 10.88,55.41 11.15,55.68 11.15,55.93 11.42,56.2 11.67,56.2 11.94,56.47 11.94,56.72 13,57.78 16.66,57.78 17.95,56.48 17.95,55.21 20.51,52.65 21.26,52.65 v1(21.54,52.37)
USB7_USB31_RX_P: length 40.8
  TOP w0.127: CN1.B11 20.36,53.03 20.48,52.91 21.26,52.91 v1(21.54,53.19) ; v1(9.43,33.65) 9.68,33.4 9.68,33.05 C1001.2
  BOTTOM w0.127: v1(9.43,33.65) 9.66,33.88 9.66,37.09 9.27,37.48 9.27,54.47 12.87,58.08 16.78,58.08 18.26,56.61 18.26,55.34 20.64,52.96 21.31,52.96 v1(21.54,53.19)
USB7_USB31_TX_N: length 21.8
  TOP w0.127: v1(12.53,36.72) 12.28,36.47 12.28,36.22 C1004.2 ; CN1.A12 14.74,52.43 14.59,52.58 13.85,52.58 v1(13.6,52.32)
  BOTTOM w0.127: v1(12.53,36.72) 12.25,37 12.25,37.55 10.71,39.08 10.71,40.72 10.89,40.9 10.89,41.28 10.71,41.46 10.71,41.84 10.89,42.02 10.89,42.4 10.71,42.57 10.71,42.96 10.89,43.13 10.89,43.51 10.71,43.69 10.71,50.74 12.59,52.62 13.3,52.62 v1(13.6,52.32)
USB7_USB31_TX_P: length 21.8
  TOP w0.127: C1003.2 11.97,36.22 11.97,36.47 v1(11.72,36.72) ; v1(13.6,53.14) 13.85,52.88 14.61,52.88 14.75,53.03 CN1.A11
  BOTTOM w0.127: v1(13.6,53.14) 13.39,52.93 12.47,52.93 10.41,50.87 10.41,38.96 11.94,37.42 11.94,36.95 v1(11.72,36.72)
USB8_USB20_N: length 72.6
  TOP w0.127: v1(30.95,32.66) 30.7,32.91 30.09,32.91 28.57,34.43 28.57,55.64 28.04,56.18 26.31,56.18 26.26,56.13 U0903.1 U0903.8 23.99,56.13 23.95,56.18 20.49,56.18 20.35,56.03 CN1.B6 ; U0801.23 45.7,17.43 45.65,17.38 45.65,16.85 45.36,16.56 45.36,16.31 45.09,16.04 44.84,16.04 44.57,15.77 44.57,15.52 44.3,15.25 44.05,15.25 43.73,14.93 43.73,14.19 44.03,13.89 44.48,13.89 v1(44.99,14.4)
  BOTTOM w0.127: v1(30.95,32.66) 31.2,32.91 34.28,32.91 34.92,32.28 34.92,32.02 35.19,31.75 35.44,31.75 36.06,31.13 36.44,31.13 36.62,30.95 37,30.95 37.18,31.13 38.73,31.13 39,30.86 39,30.61 39.27,30.34 39.52,30.34 39.79,30.07 39.79,29.82 40.06,29.55 40.31,29.55 40.58,29.28 40.58,29.03 40.85,28.76 41.1,28.76 41.88,27.98 41.88,26.8 41.7,26.62 41.7,26.24 41.88,26.06 41.88,25.68 41.7,25.51 41.7,25.13 41.88,24.95 41.88,21.96 42.59,21.25 42.59,18.23 43.63,17.19 45.31,17.19 45.92,16.58 45.92,14.44 45.66,14.19 45.2,14.19 v1(44.99,14.4) 44.73,14.14 43.93,14.14 L0901.1 43.59,14.48 R0905.1
USB8_USB20_P: length 72.6
  TOP w0.127: CN1.B5 20.34,56.63 20.49,56.48 23.95,56.48 24,56.53 U0903.7 U0903.2 26.29,56.53 26.33,56.48 28.16,56.48 28.87,55.77 28.87,34.56 30.22,33.21 30.7,33.21 v1(30.95,33.46) ; v1(44.99,13.58) 43.91,13.58 43.43,14.06 43.43,15.05 45.35,16.97 45.35,17.35 45.3,17.4 U0801.22
  BOTTOM w0.127: R0906.1 43.59,13.49 L0901.2 43.94,13.84 44.73,13.84 v1(44.99,13.58) 45.28,13.88 45.79,13.88 46.22,14.31 46.22,16.7 45.43,17.49 43.76,17.49 42.89,18.36 42.89,21.38 42.18,22.09 42.18,28.11 38.86,31.44 36.19,31.44 34.41,33.21 31.2,33.21 v1(30.95,33.46)
USB8_USB31_RX_N: length 34.9
  TOP w0.127: v1(34.66,43.83) 34.35,44.14 33.73,44.14 33.14,43.55 33.14,41.94 33.32,41.76 33.32,41.38 33.14,41.2 33.14,40.82 33.32,40.64 33.32,40.26 33.14,40.09 33.14,39.7 33.32,39.53 33.32,39.15 33.14,38.97 33.14,29.52 C0712.1 ; CN1.B15 20.36,50.63 20.5,50.78 21.3,50.78 v1(21.55,50.52)
  BOTTOM w0.127: v1(34.66,43.83) 34.4,44.09 29.66,44.09 22.96,50.79 21.82,50.79 v1(21.55,50.52)
USB8_USB31_RX_N_C: length 5
  TOP w0.127: U0701.11 33.98,24.1 33.7,24.38 33.7,26.86 33.19,27.37 33.19,27.97 C0712.2
USB8_USB31_RX_P: length 34.9
  TOP w0.127: v1(34.66,44.64) 34.46,44.44 33.6,44.44 32.84,43.68 32.84,29.47 C0713.1 ; v1(21.55,51.34) 21.3,51.08 20.51,51.08 20.36,51.23 CN1.B14
  BOTTOM w0.127: v1(34.66,44.64) 34.4,44.39 29.79,44.39 23.08,51.1 21.79,51.1 v1(21.55,51.34)
USB8_USB31_RX_P_C: length 5
  TOP w0.127: C0713.2 32.89,27.92 32.89,27.25 33.4,26.74 33.4,24.25 33.63,24.01 U0701.12
USB8_USB31_TX_N: length 37.7
  TOP w0.127: C0710.1 34.89,33.35 34.89,37.36 v1(35.1,37.56) ; v1(13.63,50.47) 13.91,50.75 14.64,50.75 14.76,50.63 CN1.A15
  BOTTOM w0.127: v1(35.1,37.56) 34.89,37.36 34.89,36.82 34.54,36.46 29.79,36.46 23.49,42.77 19.6,42.77 17.27,45.1 17.27,49.85 16.4,50.72 13.88,50.72 v1(13.63,50.47)
USB8_USB31_TX_N_C: length 8.7
  TOP w0.127: U0701.8 35.03,23.96 35.02,23.97 35.02,24.81 34.74,25.09 34.74,26.76 34.94,26.96 34.94,31.75 C0710.2
USB8_USB31_TX_P: length 37.6
  TOP w0.127: C0711.1 34.59,33.25 34.59,37.25 v1(34.28,37.56) ; CN1.A14 14.76,51.23 14.58,51.05 13.87,51.05 v1(13.63,51.29)
  BOTTOM w0.127: v1(34.28,37.56) 34.59,37.25 34.59,36.95 34.41,36.77 32.24,36.77 32.06,36.95 31.68,36.95 31.5,36.77 31.1,36.77 30.92,36.95 30.54,36.95 30.36,36.77 29.92,36.77 29.59,37.09 29.59,37.35 29.32,37.62 29.07,37.62 23.62,43.07 19.73,43.07 17.57,45.23 17.57,49.98 16.53,51.02 13.9,51.02 v1(13.63,51.29)
USB8_USB31_TX_P_C: length 8.8
  TOP w0.127: C0711.2 34.64,31.75 34.64,27.09 34.44,26.88 34.44,24.96 34.72,24.68 34.72,23.97 34.68,23.93 U0701.9
USB9_USB31_RX_N: length 35.1
  TOP w0.127: CN1.B18 20.36,48.83 20.51,48.98 21.94,48.98 v1(22.19,48.72) ; C0709.1 36.57,29.52 36.57,35.22 36.39,35.4 36.39,35.78 36.57,35.96 36.57,36.52 37.71,37.66 37.71,38.26 37.54,38.43 37.54,38.82 37.71,38.99 37.71,39.37 37.54,39.55 37.54,39.93 37.71,40.11 37.71,41.9 37.31,42.31 36.87,42.31 v1(36.57,42)
  BOTTOM w0.127: v1(36.57,42) 36.32,42.26 29.97,42.26 23.26,48.96 22.43,48.96 v1(22.19,48.72)
USB9_USB31_RX_N_C: length 4.9
  TOP w0.127: C0709.2 36.54,27.94 36.54,25.11 36.1,24.67 36.1,23.88 36.08,23.86 U0701.5
USB9_USB31_RX_P: length 35.2
  TOP w0.127: C0708.1 36.87,29.47 36.87,36.39 38.02,37.53 38.02,42.03 37.43,42.61 36.77,42.61 v1(36.57,42.82) ; CN1.B17 20.36,49.43 20.5,49.28 21.94,49.28 v1(22.19,49.54)
  BOTTOM w0.127: v1(36.57,42.82) 36.32,42.56 30.09,42.56 23.39,49.27 22.46,49.27 v1(22.19,49.54)
USB9_USB31_RX_P_C: length 4.9
  TOP w0.127: U0701.4 36.43,23.86 36.41,23.88 36.41,24.54 36.85,24.99 36.85,27.94 C0708.2
USB9_USB31_TX_N: length 44.5
  TOP w0.127: v1(13.63,55.92) 13.88,56.18 14.6,56.18 14.75,56.03 CN1.A6 ; v1(38.45,35.69) 38.7,35.43 38.7,33.3 C0707.1
  BOTTOM w0.127: v1(38.45,35.69) 38.73,35.97 38.73,36.87 36.87,38.73 29.18,38.73 24.05,43.86 20.54,43.86 19.58,44.82 19.58,48.75 19.4,48.92 19.4,49.31 19.58,49.48 19.58,50 18.34,51.24 18.09,51.24 17.82,51.51 17.82,51.76 17.55,52.03 17.3,52.03 17.03,52.3 17.03,52.55 16.76,52.82 16.76,55.67 16.2,56.23 13.93,56.23 v1(13.63,55.92)
USB9_USB31_TX_N_C: length 9.2
  TOP w0.127: C0707.2 38.7,31.75 38.7,28.44 37.54,27.27 37.54,24.38 37.13,23.97 U0701.2
USB9_USB31_TX_P: length 44.5
  TOP w0.127: v1(13.63,56.74) 13.88,56.48 14.6,56.48 14.75,56.63 CN1.A5 ; v1(39.26,35.69) 39.01,35.43 39.01,33.3 C0706.1
  BOTTOM w0.127: v1(13.63,56.74) 13.83,56.53 16.33,56.53 17.06,55.8 17.06,52.95 19.88,50.13 19.88,44.95 20.67,44.16 24.17,44.16 29.31,39.03 37,39.03 39.03,37 39.03,35.91 v1(39.26,35.69)
USB9_USB31_TX_P_C: length 9.2
  TOP w0.127: U0701.1 37.48,23.89 37.84,24.25 37.84,27.14 39.01,28.31 39.01,31.75 C0706.2
USB10_USB20_N: length 44.7
  TOP w0.127: v1(22.22,45.12) 21.96,45.38 20.49,45.38 20.34,45.23 CN1.B24
  BOTTOM w0.127: v1(22.22,45.12) 22.48,45.38 24.05,45.38 29.71,39.72 38.35,39.72 38.96,39.1 38.96,38.85 39.23,38.58 39.48,38.58 39.75,38.31 39.75,38.06 40.02,37.79 40.27,37.79 40.54,37.52 40.54,37.27 40.81,37 41.06,37 43.02,35.04 59.58,35.04
USB10_USB20_P: length 44.3
  TOP w0.127: CN1.B23 20.35,45.83 20.49,45.69 21.97,45.69 v1(22.22,45.94)
  BOTTOM w0.127: 59.58,35.35 43.15,35.35 38.47,40.02 29.84,40.02 24.17,45.69 22.47,45.69 v1(22.22,45.94)
USB10_USB31_RX_N: length 48.2
  TOP w0.127: v1(21.55,46.92) 21.3,47.18 20.48,47.18 20.34,47.03 CN1.B21 ; v1(56,36.33) 56.27,36.59 56.92,36.59 57.6,35.91 57.6,33.42 59.58,31.44
  BOTTOM w0.127: v1(56,36.33) 55.73,36.59 42.87,36.59 38.75,40.71 30.12,40.71 23.67,47.16 21.79,47.16 v1(21.55,46.92)
USB10_USB31_RX_P: length 48.1
  TOP w0.127: 59.58,31.87 57.91,33.55 57.91,36.03 57.04,36.9 56.24,36.9 v1(56,37.14) ; v1(21.55,47.74) 21.3,47.48 20.5,47.48 20.35,47.63 CN1.B20
  BOTTOM w0.127: v1(56,37.14) 55.76,36.9 43,36.9 38.88,41.01 30.25,41.01 23.79,47.46 21.83,47.46 v1(21.55,47.74)
USB10_USB31_TX_N: length 58.9
  TOP w0.127: CN1.A18 14.76,48.83 14.61,48.98 13.31,48.98 v1(13.06,48.72)
  BOTTOM w0.127: 59.58,32.48 59.18,32.07 56.92,32.07 54.99,34 37.18,34 35.66,35.52 29.08,35.52 24.71,39.9 18.84,39.9 15.06,43.68 15.06,48.45 14.57,48.94 13.27,48.94 v1(13.06,48.72)
USB10_USB31_TX_P: length 59.4
  TOP w0.127: CN1.A17 14.76,49.43 14.61,49.28 13.31,49.28 v1(13.06,49.54)
  BOTTOM w0.127: v1(13.06,49.54) 13.35,49.24 14.7,49.24 15.36,48.58 15.36,43.81 18.97,40.2 24.84,40.2 29.21,35.83 35.78,35.83 37.31,34.31 39.58,34.31 39.76,34.48 40.14,34.48 40.32,34.31 40.7,34.31 40.87,34.48 41.26,34.48 41.43,34.31 41.94,34.31 42.12,34.48 42.5,34.48 42.68,34.31 55.11,34.31 57.04,32.38 59.05,32.38 59.58,32.91
USB_OC4_R_N: length 52.3
  TOP w0.127: v1(14.22,43.58) 14.37,43.43 CN1.A27 ; v1(44.44,39.9) 44.44,26.78 R7430.2 43.56,25.89 43.56,21.99 43.7,21.84 U0801.7
  L3_IN1 w0.127: v1(44.44,39.9) 43.73,39.18 24.56,39.18 23.72,40.02 21.08,40.02 18.03,43.07 14.73,43.07 v1(14.22,43.58)
USB_OC5_R_N: length 34.7
  TOP w0.127: U1101.1 27.41,24.13 27.78,24.5 29.25,24.5 29.59,24.83 29.59,31.13 29.2,31.51 25.9,31.51 24.63,32.78 v1(24.63,37.48) ; CN1.A32 14.06,40.43 v1(13.46,41.04)
  L3_IN1 w0.127: v1(24.63,37.48) 24.12,37.99 21.2,37.99 17.65,41.55 13.96,41.55 v1(13.46,41.04)
USB_TYPEC_CHG: length 6.4
  TOP w0.127: R1107.2 19.46,26.65 v1(22.47,23.64) 23.12,22.99 U1101.7
USB_TYPEC_CHG_HI: length 11.4
  TOP w0.127: Q1101.D 20.27,28.79 20.42,28.64 v1(20.42,27.04) ; U1101.8 22.48,22.49 v1(20.19,24.78) R1102.2 R1108.2
  BOTTOM w0.127: v1(20.42,27.04) 20.19,26.81 v2(20.19,25.65) v1(20.19,24.78)
USB_TYPEC_CHG_HI_D: length 18
  TOP w0.127: R74425.2 41.02,28.59 v1(40.63,28.21) ; U0801.17 43.3,17.41 43.05,17.16 v1(41.78,17.16)
  BOTTOM w0.127: v1(40.63,28.21) v2(40.63,27.32) 40.13,26.81 40.13,23.49 41.22,22.39 41.22,20.77 41.73,20.26 41.73,17.21 v1(41.78,17.16)
USB_TYPEC_CHG_HI_EN: length 3.9
  TOP w0.127: Q1101.G v1(18.08,31.12) 17.99,31.2 R1112.2 R7423.2 18.83,33.62 R74424.1
USB_TYPEC_CHG_HI_EN_R: length 14.6
  TOP w0.127: CN1.A28 12.84,42.83 v1(12.31,42.31) ; R74424.2 v1(17.37,33.8)
  BOTTOM w0.127: v1(12.31,42.31) 12.31,38.5 14.17,36.64 14.52,36.64 v1(17.37,33.8)
USB_TYPEC_EN: length 6.5
  TOP w0.127: U1101.6 24.91,23.87 24.63,24.15 v1(24.28,24.15) 22.47,24.15 21.33,25.29 R1105.2
USB_TYPEC_REF: length 7.2
  TOP w0.127: v1(17.9,23.77) R1111.1 19.23,23.16 20.16,23.16 21.83,21.49 U1101.10
USB_TYPEC_REF_RTN1: length 5.5
  TOP w0.127: U1101.9 22.06,21.99 v1(20.29,23.77) R1111.2
USBPWR_1_F: length 5.2
  L4_VCC w0.508: TC1401.1 58.82,19.78 ; TC1401.1 58.82,21.11 ; TC1401.1 57.5,21.11 ; TC1401.1 57.5,19.78
  BOTTOM w0.508: 59.58,20.44 TC1401.1
  vias: v1(54.73,18.81) v1(54.73,17.8) v1(54.73,16.78) v1(54.73,15.77) v1(54.73,14.75) v1(55.62,18.81) v1(55.62,17.8) v1(55.62,16.78) v1(55.62,15.77) v1(55.62,14.75)
N24251455: length 7.8
  TOP w0.127: U0801.30 47.15,20.17 49.91,22.93 49.91,23.77 50.29,24.15 v1(50.29,25.42) R74426.2

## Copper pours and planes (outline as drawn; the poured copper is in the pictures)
+5V_S5 on TOP (solid shape): 27.43,30.5 27.43,24.73 27.12,24.43 27.12,23.46 27.02,23.36 25.24,23.36 25.19,23.41 25.19,24.02 24.35,24.86 24.35,30.47 24.51,30.62 27.3,30.62
+5V_S5 on TOP (solid shape): 58.8,29.1 59.3,29.1 59.56,28.85 59.56,27.96 59.05,27.45 59.05,26.94 58.73,26.62 53.91,26.62 53.72,26.81 53.72,29.1 53.97,29.35 58.54,29.35
+5V_S5 on TOP (solid shape): 52.57,22.37 52.57,21.29 52.56,21.25 52.56,21.23 52.56,21.2 52.57,21.17 52.57,19.32 52.5,19.24 46.8,19.24 46.55,19.27 46.55,19.48 46.8,19.48 46.8,19.67 46.55,19.67 46.55,19.88 46.8,19.93 47.26,19.93 49.96,22.62 52.32,22.62
+5V_S5 on BOTTOM (solid shape): 52.57,22.37 52.57,19.45 52.45,19.32 46.48,19.32 46.35,19.45 46.35,21.35 46.48,21.48 50.92,21.48 51.18,21.73 51.18,22.37 51.3,22.5 52.45,22.5
+5V_S5 on BOTTOM (solid shape): outline of 455 points within 1.65,46.75 6.98,59.96
+5V_S5 on L3_IN1 (solid shape): outline of 4026 points within 1.52,24.15 29.84,61.61
+5V_S5 on L4_VCC: 2.26,61.61 5.6,61.61 5.96,61.25 5.96,57.15 5.73,56.91 4.57,56.91 4.47,56.89 4.39,56.84 4.01,56.46 3.95,56.38 3.93,56.28 3.93,47.11 3.7,46.88 2.41,46.88 2.31,46.86 2.23,46.81 1.97,46.55 1.92,46.47 1.9,46.37 1.9,37.48 1.92,37.38 1.97,37.3 5.02,34.25 5.1,34.2 5.2,34.18 7.38,34.18 8.58,32.98 8.66,32.93 8.76,32.91 21.86,32.91 24.58,30.19 24.66,30.14 24.76,30.12 73.42,30.12 75.63,27.9 75.72,27.85 75.81,27.83 80.39,27.83 80.48,27.85 80.56,27.9 81.25,28.59 83.18,28.59 83.28,28.61 83.36,28.67 83.92,29.23 89.81,29.23 90.42,28.61 90.42,22.35 90.06,21.99 84.58,21.99 84.48,21.97 84.4,21.91 81.8,19.32 62.46,19.32 59.86,21.91 59.78,21.97 59.68,21.99 56.13,21.99 56.03,21.97 55.95,21.91 53.36,19.32 31.21,19.32 29.51,21.02 29.43,21.08 29.33,21.1 24.25,21.1 24.15,21.08 24.07,21.02 22.8,19.75 22.75,19.67 22.73,19.58 22.73,15.36 19.45,12.08 1.88,12.08 1.52,12.44 1.52,60.87 ; 5 cut-outs
+5V_VCCPD_VBUS_F1 on TOP (solid shape): 19.93,7.38 19.93,2.28 19.78,2.13 17.49,2.13 17.19,2.43 17.19,7.26 17.57,7.64 19.68,7.64
+5V_VCCPD_VBUS_F1 on TOP (solid shape): 11.42,10.18 11.42,8.91 10.79,8.27 10.54,8.27 10.41,8.4 10.41,10.69 10.54,10.81 10.79,10.81
+5V_VCCPD_VBUS_F1 on TOP (solid shape): 27.12,21.12 27.12,20.41 28.95,18.58 28.95,17.52 28.8,17.37 26.03,17.37 25.83,17.57 25.83,18.03 26.26,18.46 26.26,21.1 26.33,21.18 27.07,21.18
+5V_VCCPD_VBUS_F1 on L4_VCC: 24.36,20.59 29.23,20.59 30.35,19.47 30.35,12.44 27.25,9.34 27.19,9.26 27.17,9.16 27.17,6.85 26.94,6.62 26.41,6.62 26.31,6.6 26.23,6.55 25.47,5.78 25.41,5.7 25.39,5.61 25.39,2.92 24.65,2.18 17.75,2.18 17.14,2.79 17.14,5.86 17.12,5.96 17.06,6.04 16.56,6.55 16.47,6.6 16.38,6.62 14.35,6.62 14.25,6.6 14.17,6.55 13.15,5.53 13.09,5.45 13.08,5.35 13.08,2.54 12.72,2.18 12.71,2.18 12.52,2.45 12.22,2.55 11.4,2.55 11.09,2.45 10.91,2.18 10.7,2.18 10.52,2.45 10.21,2.55 9.4,2.55 9.09,2.45 8.91,2.18 8.71,2.18 8.52,2.45 8.22,2.55 7.4,2.55 7.15,2.48 6.96,2.3 6.73,2.54 6.73,4.08 6.71,4.18 6.65,4.26 5.84,5.08 5.84,5.86 5.82,5.96 5.76,6.04 2.41,9.39 2.41,11.34 2.64,11.57 19.55,11.57 19.65,11.59 19.73,11.65 23.16,15.08 23.22,15.16 23.24,15.26 23.24,19.47 ; 3 cut-outs
+5V_VCCPD_VBUS_F2 on TOP (solid shape): 42.16,9.03 42.16,4.31 42.01,4.16 39.72,4.16 39.41,4.46 39.41,9.08 39.62,9.29 41.9,9.29
+5V_VCCPD_VBUS_F2 on TOP (solid shape): 34.67,10.69 34.67,8.4 34.54,8.27 34.28,8.27 33.65,8.91 33.65,10.18 34.28,10.81 34.54,10.81
+5V_VCCPD_VBUS_F2 on TOP (solid shape): 48.94,18.94 48.94,18.08 48.76,17.9 47.66,17.9 47.62,17.91 47.59,17.91 47.13,17.91 47.09,17.95 47.09,18.28 46.93,18.43 46.8,18.43 46.5,18.47 46.5,18.68 46.8,18.68 46.8,18.87 46.5,18.87 46.5,19.02 46.56,19.08 46.8,19.09 48.79,19.09
+5V_VCCPD_VBUS_F2 on BOTTOM (solid shape): 52.32,18.81 52.32,18.18 52.06,17.92 47.24,17.92 47.11,18.05 47.11,18.94 47.24,19.07 52.06,19.07
+5V_VCCPD_VBUS_F2 on L4_VCC: 31.21,18.81 49.93,18.81 50.29,18.45 50.29,12.17 50.26,12.16 50.23,12.13 49.93,11.83 47.87,11.83 47.78,11.81 47.69,11.75 46.93,10.99 46.88,10.91 46.86,10.81 46.86,4.82 46.24,4.21 39.72,4.21 39.36,4.57 39.36,6.11 39.34,6.21 39.29,6.29 38.91,6.67 38.83,6.73 38.73,6.75 36.82,6.75 36.73,6.73 36.64,6.67 36.01,6.04 35.95,5.96 35.94,5.86 35.94,5.08 35.12,4.26 35.07,4.18 35.05,4.08 35.05,2.66 34.89,2.51 34.8,2.54 34.7,2.55 33.88,2.55 33.57,2.45 33.39,2.18 33.18,2.18 33,2.45 32.69,2.55 31.88,2.55 31.57,2.45 31.39,2.18 31.19,2.18 31,2.45 30.7,2.55 29.88,2.55 29.67,2.5 29.5,2.37 29.2,2.66 29.2,3.95 29.18,4.05 29.13,4.13 28.32,4.95 28.32,6.11 28.3,6.21 28.24,6.29 27.68,6.85 27.68,9.06 30.78,12.16 30.84,12.24 30.86,12.34 30.86,18.45 ; 4 cut-outs
+12V_DSW on TOP (solid shape): outline of 625 points within 4.36,36.92 10.31,56.86
+12V_DSW on L4_VCC: outline of 94 points within 4.44,10.69 127.03,63.48
GND on TOP (solid shape): 28.19,55.01 28.19,52.34 28.06,52.21 27.68,52.21 27.55,52.34 27.55,55.01 27.68,55.14 28.06,55.14
GND on TOP (solid shape): 45.46,9.03 45.46,4.31 45.31,4.16 43.02,4.16 42.72,4.46 42.72,9.03 42.97,9.29 45.21,9.29
GND on TOP (solid shape): 23.24,7.38 23.24,2.28 23.08,2.13 20.8,2.13 20.49,2.43 20.49,7.38 20.75,7.64 22.98,7.64
GND on TOP (solid shape): 37.33,23.21 37.33,21.78 37.26,21.71 33.85,21.71 33.75,21.81 33.75,23.21 33.83,23.28 37.26,23.28
GND on TOP (solid shape): 13.33,9.92 13.33,8.27 13.08,8.02 12.06,8.02 11.93,8.15 11.93,9.8 12.31,10.18 13.08,10.18
GND on TOP (solid shape): 14.6,33.8 14.6,33.42 14.35,33.16 13.71,33.16 13.46,32.91 13.08,32.91 12.95,33.04 12.95,34.18 13.2,34.43 13.96,34.43
GND on TOP (solid shape): 29.2,16.91 29.2,15.77 28.95,15.51 26.03,15.51 25.78,15.77 25.78,16.86 26.03,17.11 29,17.11
GND on TOP (solid shape): 29.38,30.78 29.38,25.23 28.93,24.78 27.81,24.78 27.73,24.86 27.73,25.47 27.96,25.7 27.96,30.9 28.14,31.08 29.08,31.08
GND on TOP (solid shape): 27.45,22.9 27.45,21.58 27.38,21.51 24.94,21.51 24.89,21.56 24.89,22.9 24.96,22.98 27.38,22.98
GND on TOP (solid shape): 33.01,9.92 33.01,8.53 32.76,8.27 31.74,8.27 31.62,8.4 31.62,9.8 32,10.18 32.76,10.18
GND on TOP (solid shape): 12.67,22.06 12.67,19.55 12.52,19.4 8,19.4 7.84,19.55 7.84,22.06 8,22.22 12.52,22.22
GND on TOP (solid shape): 23.97,29.63 23.97,24.53 23.92,24.48 22.5,24.48 21.97,25.01 21.97,28.47 23.26,29.76 23.84,29.76
GND on TOP (solid shape): 59.56,29.99 59.56,29.53 59.43,29.4 58.72,29.4 58.39,29.74 57.97,29.74 57.93,29.75 57.91,29.75 57.88,29.75 57.85,29.74 53.84,29.74 53.59,29.99 53.59,31.77 53.97,32.15 57.4,32.15
GND on TOP (solid shape): 53.77,21.61 53.77,18.79 53.56,18.58 53.56,17.85 53.13,17.42 53.13,14.39 52.8,14.06 50.97,14.06 50.16,14.88 50.16,16.2 49.07,17.29 49.07,18.02 49.07,18.02 49.07,18.64 49.22,18.79 52.6,18.79 52.95,19.14 52.95,21.53 53.21,21.78 53.59,21.78
GND on TOP (solid shape): 46.2,20.87 46.2,18.28 46.1,18.18 44.7,18.18 44.6,18.08 44.6,17.42 44.52,17.34 44.04,17.34 43.99,17.38 43.99,18.12 43.94,18.18 43.15,18.18 43.05,18.08 42.51,18.08 42.44,18.15 42.44,19.02 42.5,19.08 43.16,19.08 43.17,19.09 43.3,19.22 43.3,19.6 43.22,19.68 42.51,19.68 42.44,19.75 42.44,20.21 42.51,20.28 43.19,20.28 43.3,20.39 43.3,20.97 43.38,21.05 46.02,21.05
GND on TOP (solid shape): outline of 132 points within 40.29,33.77 93.47,46.88
GND on TOP (solid shape): outline of 248 points within 1.28,65.55 8.29,72.56
GND on TOP (solid shape): outline of 248 points within 15.29,14.17 22.29,21.17
GND on TOP (solid shape): outline of 1059 points within 0.51,0.51 148.99,74.49
GND on BOTTOM (solid shape): 50.92,23.26 50.92,22.12 50.79,21.99 46.35,21.99 46.1,22.24 46.1,22.88 46.73,23.51 50.67,23.51
GND on BOTTOM (solid shape): 52.32,17.04 52.32,14.5 51.81,13.99 50.92,13.99 50.16,14.75 50.16,15.26 49.02,16.4 49.02,16.91 49.91,17.8 51.56,17.8
GND on BOTTOM (solid shape): 27.45,22.9 27.45,21.58 27.38,21.51 24.94,21.51 24.89,21.56 24.89,22.9 24.96,22.98 27.38,22.98
GND on BOTTOM (solid shape): 12.67,22.06 12.67,19.55 12.52,19.4 8,19.4 7.84,19.55 7.84,22.06 8,22.22 12.52,22.22
GND on BOTTOM (solid shape): 35.53,23.23 37.28,23.23 37.36,23.16 37.36,22.14 36.93,21.71 36.93,21.2 36.82,21.1 34.56,21.1 34.46,21.2 34.46,21.66 34.36,21.76 34,21.76 33.85,21.91 33.85,22.95 34.31,23.41 34.31,23.92 34.44,24.05 34.72,24.05
GND on BOTTOM (solid shape): outline of 235 points within 40.29,33.77 93.47,46.88
GND on BOTTOM (solid shape): outline of 248 points within 1.28,65.55 8.29,72.56
GND on BOTTOM (solid shape): outline of 248 points within 15.29,14.17 22.29,21.17
GND on BOTTOM (solid shape): outline of 254 points within 0.92,65.19 8.65,72.92
GND on BOTTOM (solid shape): outline of 1127 points within 0.51,0.51 148.98,74.49
GND on L3_IN1 (solid shape): 37.84,23.61 37.84,21.18 37.64,20.97 37.02,20.97 37.01,20.98 36.85,21.01 36.69,20.98 36.68,20.97 34.46,20.97 34.45,20.98 34.37,21.01 34.28,21.02 34.19,21.01 34.11,20.98 34.1,20.97 33.47,20.97 33.29,21.15 33.29,23.89 33.42,24.02 37.43,24.02
GND on L3_IN1 (solid shape): 16.53,57.45 16.53,46.33 16.32,46.12 14.12,46.12 14.01,46.22 14.01,50.14 14.09,50.24 14.13,50.37 14.14,50.47 14.14,51.29 14.13,51.39 14.09,51.51 14.01,51.62 14.01,52.03 14.07,52.12 14.1,52.22 14.11,52.32 14.11,53.14 14.1,53.24 14.07,53.34 14.01,53.43 14.01,55.57 14.09,55.69 14.13,55.83 14.14,55.9 14.14,56.74 14.09,56.94 14.01,57.07 14.01,57.5 14.07,57.55 16.43,57.55
GND on L3_IN1 (solid shape): 21.13,57.34 21.13,53.51 21.08,53.42 21.04,53.32 21.03,53.21 21.03,52.37 21.07,52.19 21.13,52.08 21.13,51.61 21.08,51.51 21.05,51.34 21.05,50.52 21.08,50.35 21.13,50.25 21.13,49.98 21.05,49.75 21.13,49.52 21.13,48.01 21.08,47.91 21.05,47.74 21.05,46.92 21.05,46.85 21.08,46.75 21.13,46.65 21.13,45.38 20.74,45 20.69,44.98 19.03,44.98 18.97,45 18.91,45.01 18.61,45.31 18.61,57.35 18.79,57.53 20.94,57.53
GND on L3_IN1 (solid shape): 12.95,25.93 12.95,25.67 11.04,23.77 9.55,23.77 9.42,23.86 9.26,23.89 8.88,23.51 9.26,23.13 9.42,23.16 9.55,23.26 13.2,23.26 13.58,22.88 13.58,21.71 13.48,21.45 13.58,21.19 13.58,19.32 13.42,19.16 13.39,19.19 13.28,19.24 13.16,19.26 12.89,19.15 12.78,18.88 12.8,18.76 12.85,18.65 12.88,18.62 12.82,18.56 8.5,18.56 7.61,19.45 7.61,22.37 7.59,22.4 7.56,22.47 7.59,22.54 7.66,22.66 7.69,22.8 7.69,22.85 7.7,22.92 7.76,22.97 7.97,23.1 8.05,23.33 7.66,23.72 7.28,23.33 7.29,23.28 7.27,23.21 7.21,23.17 7.12,23.13 7.05,23.08 6.98,23.05 6.9,23.08 6.73,23.26 6.05,23.26 5.83,23.48 5.83,25.13 5.99,25.29 6.6,25.29 6.96,25.65 7,25.63 7.11,25.56 7.23,25.54 7.38,25.57 7.5,25.66 8.15,26.31 12.57,26.31
GND on L3_IN1 (solid shape): outline of 540 points within 23.74,33.76 93.47,53.87
GND on L3_IN1 (solid shape): outline of 969 points within 30.22,21.23 59.3,37.74
GND on L3_IN1 (solid shape): outline of 6202 points within 0.51,0.51 148.97,74.49
GND on L2_GND1: outline of 195 points within 0.51,0.14 148.99,74.49 ; 193 cut-outs
GND on L4_VCC: outline of 216 points within 0.51,0.14 148.99,74.49
GND on L4_VCC: 63.09,18.81 75.71,18.81 76.07,18.45 76.07,9.8 76.09,9.7 76.14,9.62 75.59,9.62 74.61,8.87 75.08,7.74 75.08,2.42 74.81,2.16 64.13,2.16 63.81,2.48 63.81,7.74 64.27,8.87 63.3,9.62 58.21,9.62 58.24,9.74 58.25,9.86 58.04,10.35 57.55,10.56 56.36,10.56 62.53,16.73 62.59,16.81 62.61,16.91 62.61,18.33 ; 1 cut-out
GND on L4_VCC: 83.03,13.1 95.65,13.1 95.95,12.79 95.98,12.77 96.01,12.75 96.01,2.64 95.52,2.16 89.86,2.16 89.59,2.42 89.59,7.74 90.06,8.87 89.09,9.62 83.99,9.62 84.02,9.74 84.03,9.86 83.82,10.35 83.33,10.56 82.54,10.56 82.54,12.61 ; 1 cut-out
GND on L5_GND2: outline of 195 points within 0.51,0.14 148.99,74.49 ; 59 cut-outs
+3P3V_LDO on L3_IN1 (solid shape): outline of 839 points within 40.43,17.31 48.91,28.08
+3P3V_MUX1_S5 on TOP (solid shape): 16.12,32.4 16.12,31.39 15.87,31.13 13.71,31.13 13.46,31.39 13.46,32.28 13.84,32.66 15.87,32.66
+3P3V_MUX1_S5 on BOTTOM (solid shape): outline of 1790 points within 2.15,7.1 17.42,31.74
+3P3V_S0 on L4_VCC: 14.2,59.2 28.85,59.2 29.2,58.84 29.2,45.74 29.24,45.54 29.35,45.38 29.99,44.74 30.15,44.63 30.35,44.59 32.51,44.59 32.7,44.63 32.87,44.74 33.5,45.38 33.61,45.54 33.65,45.74 33.58,45.99 33.4,46.18 33.4,47.03 33.75,47.39 39.28,47.39 39.56,47.02 40,46.88 90.86,46.88 94.96,42.79 95.09,42.68 95.24,42.61 95.24,39.87 94.89,39.51 85.51,39.51 85.51,39.66 85.52,39.8 81.97,43.35 78.42,39.8 78.43,39.66 78.43,39.51 27.02,39.51 22.27,44.27 22.19,44.32 22.09,44.34 11.4,44.34 10.84,44.9 10.76,44.96 10.66,44.98 4.67,44.98 4.44,45.21 4.44,54.37 9.27,54.37 9.36,54.39 9.44,54.45 ; 11 cut-outs
+3P3V_S5 on TOP (solid shape): 16.25,34.56 16.25,33.29 16.12,33.16 15.11,33.16 14.98,33.29 14.98,34.56 15.11,34.69 16.12,34.69
+3P3V_S5 on TOP (solid shape): 27.3,55.34 27.3,50.31 27.17,50.18 25.79,50.18 25.66,50.31 25.66,54 25.65,54.02 25.65,54.53 25.72,54.75 25.65,54.98 25.65,55.49 25.72,55.56 26.26,55.56 26.37,55.57 26.48,55.6 26.49,55.6 27.03,55.6
+3P3V_S5 on BOTTOM (solid shape): outline of 1518 points within 1.39,19.63 28.32,62.63
